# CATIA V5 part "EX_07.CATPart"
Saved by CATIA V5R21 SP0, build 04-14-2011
Part number: Part1
Bounding box of the stored display mesh (mm): x -188.73 to 188.73, y 0 to 20, z -74.98 to 74.98
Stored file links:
  G:\CATIA\Class\Class_3D\EX_07.CATPart
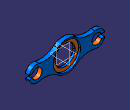
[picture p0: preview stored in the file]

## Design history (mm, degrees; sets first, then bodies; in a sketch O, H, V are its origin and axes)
Body1 (main body)
  Sketch1 on zx-plane, origin (0, 0, 0), H (-1, 0, 0), V (0, 0, 1)
    arc A1 centre (0, 0) radius 75 from (46.25, 59.0418) to (-46.25, 59.0418) ccw
    arc A2 centre (150, 0) radius 40 from (188.7298, 10) to (140.4222, 38.8364) ccw
    point P1 (150, 0)
    arc A3 centre (-150, 0) radius 40 from (-140.4222, 38.8364) to (-188.7298, 10) ccw
    point P2 (-150, 0)
    arc A4 centre (-114.0833, 145.6365) radius 110 from (-140.4222, 38.8364) to (-46.25, 59.0418) ccw
    point P3 (-140.4222, 38.8364)
    point P4 (-46.25, 59.0418)
    arc A5 centre (114.0833, 145.6365) radius 110 from (46.25, 59.0418) to (140.4222, 38.8364) ccw
    point P6 (46.25, 59.0418)
    point P7 (140.4222, 38.8364)
    point P9 (-140.4222, -38.8364)
    point P10 (-46.25, -59.0418)
    point P11 (46.25, -59.0418)
    point P12 (140.4222, -38.8364)
    arc A6 centre (0, 0) radius 75 from (46.25, -59.0418) to (-46.25, -59.0418) cw
    arc A7 centre (-114.0833, -145.6365) radius 110 from (-140.4222, -38.8364) to (-46.25, -59.0418) cw
    arc A8 centre (114.0833, -145.6365) radius 110 from (46.25, -59.0418) to (140.4222, -38.8364) cw
    arc A9 centre (150, 0) radius 40 from (140.4222, -38.8364) to (188.7298, -10) ccw
    point P16 (140.4222, -38.8364)
    point P17 (188.7298, -10)
    point P18 (188.7298, 10)
    arc A10 centre (150, 0) radius 25 from (172.9129, 10) to (172.9129, -10) ccw
    point P19 (172.9129, -10)
    point P20 (172.9129, 10)
    line L1 (172.9129, 10) -> (188.7298, 10)
    line L2 (172.9129, -10) -> (188.7298, -10)
    point P21 (-172.9129, -10)
    point P22 (-172.9129, 10)
    arc A11 centre (-150, 0) radius 25 from (-172.9129, 10) to (-172.9129, -10) cw
    point P24 (-188.7298, -10)
    line L3 (-172.9129, -10) -> (-188.7298, -10)
    point P25 (-188.7298, 10)
    line L4 (-172.9129, 10) -> (-188.7298, 10)
    arc A12 centre (-150, 0) radius 40 from (-188.7298, -10) to (-140.4222, -38.8364) ccw
    radius A1 = 75
    radius A2 = 40
    radius A3 = 40
    distance P1 V = 150
    distance V P2 = 150
    radius A4 = 110
    radius A5 = 110
    radius A10 = 25
    coincidence: P1 H, P2 H, A3 A12, P12 P16
    tangency: A4 A3, A4 A1, A5 A1, A5 A2, A9 A8
    symmetry: P3 P9 H, P4 P10 H, P6 P11 H, P7 P12 H, A1 A6 H, A4 A7 H, A5 A8 H, P19 P21 V, P20 P22 V, A10 A11 V, P17 P24 V, L2 L3 V, P18 P25 V, L1 L4 V
    horizontal: L1 H
  Pad1: profile Sketch1, direction (0, 1, 0), length 20
  Sketch2 on end face of Pad1, origin (0, 20, 0), H (-1, 0, 0), V (0, 0, 1)
    circle A1 centre (0, 0) radius 50
    radius A1 = 50
  Pocket1: profile Sketch2, direction (0, -1, 0), length 20
  Sketch3 on end face of Pad1, origin (0, 20, 0), H (-1, 0, 0), V (0, 0, 1)
    circle A1 centre (0, 0) radius 67.8
    circle A2 centre (0, 0) radius 50
    radius A2 = 50
    radius A1 = 67.8
  Pocket2: profile Sketch3, direction (0, -1, 0), length 10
